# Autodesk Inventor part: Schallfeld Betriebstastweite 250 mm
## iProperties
Shininess: 20.0
Length Units: 11269
Angle Units: 11279
Time Units: 11290
Mass Units: 11283
Length Display Precision: 3
Angle Display Precision: 2
Part Number: Schallfeld Betriebstastweite 250 mm
Material: Lexan (klar)
Document SubType Name: Modellieren
Description: Schallfeld 0,25 m
Checked By: Alves
Created: 2005-08
Designer: Klein
Manufacturer: Standard
Standards Organization: Custom
Density: 0.0
Volumn: 0.0
Area: 0.0
PropertySet Name: Model Information
Control State: 0
Master: False
Checked Out: False
Last Check In By: Kramp
Last Check In Date: 2005-08-11
BESTELLNUMMER: 0,25 m
ME: ST
Title: Schallfelder
Author: Klein
Comments: keine Bemerkung
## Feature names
1. Blindzone_Aussenglocke [Revolution]
